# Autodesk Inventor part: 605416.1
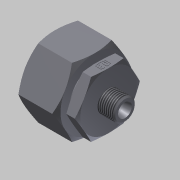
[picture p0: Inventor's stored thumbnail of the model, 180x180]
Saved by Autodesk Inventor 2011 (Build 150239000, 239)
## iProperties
Created: 2014-08
Part Number: 605416.1
Material: Сталь
Document SubType Name: Modeling
Designer: dorohin
Mass: 529.336 g
Surface Area: 166.813 cm^2
Volume: 67.4314 cm^3
Density: 7.85 g/cm^3
Стандарт преобразования: STEP AP203
Имя файла: C:/Users/dorohin/Documents/EO Tube end reducer RED30_08SOMDCF.stp
Постпроцессор: Build: 309, Release: 2011 SP2 - Date: Thu 04/28/2011
Отправленные единицы: миллиметр
Неопределенность: 1.0000000000000002e-06
Author: dorohin
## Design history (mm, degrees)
feature "БазТело1"
feature "Резьба1" dims "d0" = 10, "d1" = 0
feature "Резьба2" dims "d2" = 10, "d3" = 0
node "1"
